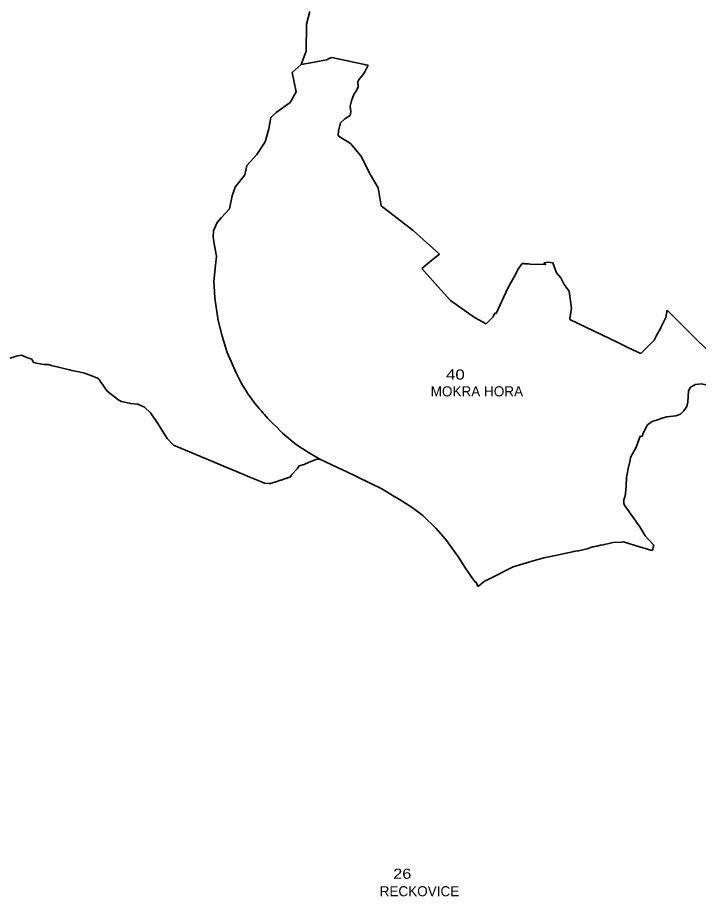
# Model space of a CAD drawing. Extents: x -610940 to -588976, y -1170376 to -1149800.
# Drawn here: x -599851 to -598167, y -1154630 to -1152456 of the extents above; entities that cross this region are included whole.
import ezdxf

# ---------------------------------------------------------------- set-up
doc = ezdxf.new("R2010")
doc.units = 0
doc.header["$LTSCALE"] = 10
doc.layers.add('54', color=7, linetype='Continuous', lineweight=35)
doc.layers.add('55', color=7, linetype='Continuous')
doc.layers.add('56', color=7, linetype='Continuous')

msp = doc.modelspace()

# ---------------------------------------------------------------- linework, layer by layer
at = {"layer": '54'}
for p, q in [((-599135.99, -1152472.46), (-599127.86, -1152441.09)), ((-599137.52, -1152539.3), (-599135.99, -1152472.46)), ((-599149.75, -1152572.15), (-599137.52, -1152539.3)), ((-599078.33, -1152556.67), (-599086.96, -1152560.86)), ((-599078.33, -1152556.67), (-599076.27, -1152555.67)), ((-599073.96, -1152554.47), (-599076.27, -1152555.67)), ((-598992.49, -1152572.39), (-599073.96, -1152554.47)), ((-599149.75, -1152572.15), (-599171.98, -1152591.48)), ((-598992.49, -1152572.39), (-598990.48, -1152572.63)), ((-598989.54, -1152572.74), (-598990.48, -1152572.63)), ((-598983.79, -1152573.41), (-598989.54, -1152572.74)), ((-599058.33, -1152748.38), (-599057.24, -1152736.51)), ((-599326.62, -1152928.89), (-599320.06, -1152896.63)), ((-598872.17, -1152982.37), (-598951.28, -1152921.55)), ((-599366.32, -1152983.61), (-599366.82, -1152998.36)), ((-598872.17, -1152982.37), (-598807.43, -1153041.24)), ((-599366.85, -1152999.45), (-599366.82, -1152998.36)), ((-599365.12, -1153010.27), (-599364.26, -1153015.45)), ((-599359.16, -1153045.95), (-599364.26, -1153015.45)), ((-599358.97, -1153047.01), (-599359.16, -1153045.95)), ((-598807.43, -1153041.24), (-598821.86, -1153053.07)), ((-598851.2, -1153077.1), (-598821.86, -1153053.07)), ((-598851.2, -1153077.1), (-598811.27, -1153121.37)), ((-598638.53, -1153125.57), (-598618.53, -1153090.33)), ((-599365.13, -1153108.85), (-599364.6, -1153119.76)), ((-599364.6, -1153119.76), (-599363.14, -1153149.9)), ((-598780.28, -1153155.74), (-598811.27, -1153121.37)), ((-598638.53, -1153125.57), (-598667.58, -1153188.27)), ((-599363.14, -1153149.9), (-599354.54, -1153205.53)), ((-598244.44, -1153179.9), (-598247.41, -1153198.37)), ((-598240.93, -1153183.4), (-598244.44, -1153179.9)), ((-598247.41, -1153198.37), (-598260.1, -1153222.84)), ((-598235.67, -1153188.66), (-598240.93, -1153183.4)), ((-598232.9, -1153191.43), (-598235.67, -1153188.66)), ((-599345.19, -1153244.24), (-599354.54, -1153205.53)), ((-598261.89, -1153226.48), (-598260.1, -1153222.84)), ((-598276.15, -1153253.71), (-598271.32, -1153244.46)), ((-598267.44, -1153237.03), (-598271.32, -1153244.46)), ((-598261.89, -1153226.48), (-598267.44, -1153237.03)), ((-598366.56, -1153260.04), (-598355.07, -1153265.54)), ((-598339.86, -1153272.82), (-598355.07, -1153265.54)), ((-598289.4, -1153266.97), (-598290.19, -1153267.76)), ((-598276.15, -1153253.71), (-598289.4, -1153266.97)), ((-598309.76, -1153287.28), (-598339.86, -1153272.82)), ((-598309.76, -1153287.28), (-598290.19, -1153267.76)), ((-599828.06, -1153297.24), (-599815.9, -1153301.5)), ((-599800.03, -1153311.45), (-599785.76, -1153314.4)), ((-599743, -1153322.93), (-599722.1, -1153327.59)), ((-599658.99, -1153345.62), (-599653.05, -1153347.81)), ((-599297.18, -1153361.27), (-599310.41, -1153334.84)), ((-599644.79, -1153358.26), (-599640.3, -1153364.57)), ((-599640.3, -1153364.57), (-599634.83, -1153372.08)), ((-599634.83, -1153372.08), (-599629.17, -1153380.26)), ((-599280.54, -1153387.7), (-599297.18, -1153361.27)), ((-599629.17, -1153380.26), (-599604.04, -1153400.11)), ((-598195.43, -1153418.01), (-598202.78, -1153429.25)), ((-599521.3, -1153434.97), (-599504.37, -1153460.09)), ((-599240.43, -1153437.86), (-599232.72, -1153446.72)), ((-599504.37, -1153460.09), (-599480.77, -1153497.73)), ((-599230.93, -1153448.77), (-599232.72, -1153446.72)), ((-598303.55, -1153484), (-598293.31, -1153463.21)), ((-598281.78, -1153454.91), (-598293.31, -1153463.21)), ((-598281.78, -1153454.91), (-598261.17, -1153448.5)), ((-598261.17, -1153448.5), (-598260.06, -1153448.16)), ((-598245.07, -1153443.49), (-598260.06, -1153448.16)), ((-599209.18, -1153470.55), (-599201.71, -1153478.03)), ((-599195.29, -1153484.45), (-599201.71, -1153478.03)), ((-598306.53, -1153492.78), (-598303.55, -1153484)), ((-599480.77, -1153497.73), (-599464.93, -1153514.21)), ((-598310.95, -1153491.41), (-598321.18, -1153519.22)), ((-598310.95, -1153491.41), (-598306.53, -1153492.78)), ((-599464.93, -1153514.21), (-599455.7, -1153518.06)), ((-599455.7, -1153518.06), (-599400.37, -1153541.23)), ((-598321.18, -1153519.22), (-598334.8, -1153544.12)), ((-599131.42, -1153556.78), (-599112.96, -1153549.04)), ((-599108.6, -1153545.04), (-599113.06, -1153542.5)), ((-599112.96, -1153549.04), (-599103.41, -1153548.24)), ((-599107.22, -1153545.82), (-599108.6, -1153545.04)), ((-599103.41, -1153548.24), (-599107.22, -1153545.82)), ((-599103.41, -1153548.24), (-599043.96, -1153576.27)), ((-598334.8, -1153544.12), (-598336.24, -1153550.96)), ((-599174.55, -1153587.84), (-599158.75, -1153571.19)), ((-599158.75, -1153571.19), (-599154.22, -1153565)), ((-599154.22, -1153565), (-599151.54, -1153564.24)), ((-599151.54, -1153564.24), (-599142.27, -1153561.36)), ((-599142.27, -1153561.36), (-599138.78, -1153560.45)), ((-599138.78, -1153560.45), (-599131.42, -1153556.78)), ((-598340.59, -1153571.58), (-598336.24, -1153550.96)), ((-599324.93, -1153572.68), (-599287.84, -1153588.14)), ((-599287.84, -1153588.14), (-599276.83, -1153592.73)), ((-599174.55, -1153587.84), (-599174.49, -1153588.06)), ((-598345.18, -1153593.29), (-598346.07, -1153614.94)), ((-599240.26, -1153607.98), (-599228.36, -1153608.86)), ((-598949.68, -1153621.51), (-598917.87, -1153641.37)), ((-598848.63, -1153687.99), (-598875.06, -1153668.48)), ((-598418.64, -1153763.65), (-598408.81, -1153761.47)), ((-598408.81, -1153761.47), (-598402.93, -1153760.17)), ((-598399.81, -1153759.48), (-598402.93, -1153760.17)), ((-598399.69, -1153760.02), (-598399.81, -1153759.48)), ((-598377.92, -1153754.94), (-598399.69, -1153760.02)), ((-598377.92, -1153754.94), (-598357.22, -1153753.45)), ((-598352.73, -1153753.39), (-598357.22, -1153753.45)), ((-598352.73, -1153753.39), (-598310.36, -1153765.86)), ((-598297.62, -1153769.61), (-598304.38, -1153767.62)), ((-598549.01, -1153792.72), (-598520.86, -1153786.71)), ((-598520.86, -1153786.71), (-598520.14, -1153786.56)), ((-598520.14, -1153786.56), (-598478.29, -1153777.62)), ((-598478.29, -1153777.62), (-598475.91, -1153777.27)), ((-598475.91, -1153777.27), (-598465.69, -1153775.56)), ((-598297.62, -1153769.61), (-598290.86, -1153771.6)), ((-598285.24, -1153773.25), (-598290.86, -1153771.6)), ((-598281.28, -1153774.42), (-598285.24, -1153773.25)), ((-598598.07, -1153806.95), (-598594.82, -1153805.96)), ((-598594.82, -1153805.96), (-598576.14, -1153800.26)), ((-598560.51, -1153795.86), (-598576.14, -1153800.26)), ((-598551.98, -1153793.37), (-598560.51, -1153795.86)), ((-598549.58, -1153792.84), (-598551.98, -1153793.37)), ((-598549.01, -1153792.72), (-598549.58, -1153792.84)), ((-598744.48, -1153816), (-598730.63, -1153836.02)), ((-598719.22, -1153853.21), (-598730.63, -1153836.02)), ((-598688.57, -1153846.89), (-598689.98, -1153847.52)), ((-598686.98, -1153846.18), (-598688.57, -1153846.89)), ((-598685.75, -1153845.63), (-598686.98, -1153846.18)), ((-598713.46, -1153861.1), (-598712.61, -1153863.28)), ((-598712.61, -1153863.28), (-598710.27, -1153861.52)), ((-598710.27, -1153861.52), (-598707.07, -1153859.11)), ((-598707.07, -1153859.11), (-598705.28, -1153857.76)), ((-598705.28, -1153857.76), (-598704.94, -1153857.51))]:
    msp.add_line(p, q, dxfattribs=at)
for points in [[(-599086.96, -1152560.86), (-599116.99, -1152566.22), (-599121.58, -1152567.01), (-599149.75, -1152572.15)], [(-599171.98, -1152591.48), (-599161.5, -1152639.33), (-599176.48, -1152665.73), (-599211.71, -1152691.23), (-599224.57, -1152703.19), (-599229.52, -1152731.35), (-599238.51, -1152763.37), (-599259.43, -1152794.76)], [(-598983.79, -1152573.41), (-598992.76, -1152591.49), (-598999.74, -1152600.82), (-599005.21, -1152607.32), (-599009.17, -1152614.28), (-599008.61, -1152628.23), (-599014.67, -1152639.22), (-599019.34, -1152645.93), (-599024.7, -1152662.11), (-599028.46, -1152675.36), (-599026.32, -1152689.13), (-599028.7, -1152698.59), (-599041.9, -1152706.56), (-599052.46, -1152716.11), (-599057.24, -1152736.51)], [(-599058.33, -1152748.38), (-599027.5, -1152767.8), (-599001.64, -1152798.37)], [(-599288.48, -1152844.94), (-599283.65, -1152821.65), (-599259.43, -1152794.76)], [(-599001.64, -1152798.37), (-598978, -1152845.22), (-598958.96, -1152877.21), (-598951.28, -1152921.55)], [(-599288.48, -1152844.94), (-599313.01, -1152875.39), (-599320.06, -1152896.63)], [(-599326.62, -1152928.89), (-599346.47, -1152950.7), (-599356.63, -1152961.87)], [(-599356.63, -1152961.87), (-599357.79, -1152964.48), (-599366.32, -1152983.61)], [(-599366.85, -1152999.45), (-599366.19, -1153003.87), (-599365.12, -1153010.27)], [(-599358.97, -1153047.01), (-599361.12, -1153068.59), (-599365.13, -1153108.85)], [(-598538.39, -1153061.2), (-598548.81, -1153063.05), (-598545.06, -1153067.23), (-598583.35, -1153066.18), (-598587.63, -1153065.54), (-598590.47, -1153065.48), (-598592.37, -1153065.41), (-598594.37, -1153065.14), (-598596.23, -1153064.99), (-598597.77, -1153064.73), (-598599.22, -1153064.51), (-598600.85, -1153064.29), (-598602.87, -1153064.16), (-598613.24, -1153078.88), (-598618.53, -1153090.33)], [(-598487.07, -1153132.6), (-598499.26, -1153116.32), (-598506.91, -1153099.64), (-598517.83, -1153087.52), (-598526.81, -1153062.81), (-598538.39, -1153061.2)], [(-598366.56, -1153260.04), (-598484.75, -1153202.93), (-598484.97, -1153199.95), (-598480.99, -1153175.42), (-598487.07, -1153132.6)], [(-598692.17, -1153213.47), (-598721.13, -1153198.42), (-598780.28, -1153155.74)], [(-598667.58, -1153188.27), (-598670.39, -1153187.02), (-598674.89, -1153195.99), (-598692.17, -1153213.47)], [(-598138.68, -1153284.83), (-598183.64, -1153241.04), (-598232.9, -1153191.43)], [(-599345.19, -1153244.24), (-599332.1, -1153284.2), (-599310.41, -1153334.84)], [(-599876.61, -1153301.06), (-599854.53, -1153293.86), (-599840.76, -1153291.57), (-599828.06, -1153297.24)], [(-599815.9, -1153301.5), (-599811.7, -1153309.01), (-599807.18, -1153309.91), (-599800.03, -1153311.45)], [(-599785.76, -1153314.4), (-599775.21, -1153314.12), (-599766.8, -1153316.47), (-599743, -1153322.93)], [(-599722.1, -1153327.59), (-599716.29, -1153328.89), (-599699.37, -1153332.67), (-599684.96, -1153336.06), (-599666.98, -1153342.68), (-599658.99, -1153345.62)], [(-599653.05, -1153347.81), (-599651.54, -1153348.75), (-599649.44, -1153351.7), (-599644.79, -1153358.26)], [(-597929.63, -1153420.15), (-597953.19, -1153411.6), (-597972.61, -1153408.03), (-598002.32, -1153411.31), (-598021.65, -1153409.35), (-598049.68, -1153401.31), (-598077.93, -1153399.17), (-598097.24, -1153392.34), (-598116.69, -1153380.62), (-598140.09, -1153366.01), (-598160.27, -1153362.42), (-598174.63, -1153363.77), (-598186.36, -1153370.45), (-598191.41, -1153379.44), (-598193.27, -1153407.64), (-598195.43, -1153418.01)], [(-599280.54, -1153387.7), (-599271.84, -1153399.75), (-599265.43, -1153408.62), (-599263.31, -1153411.56)], [(-599604.04, -1153400.11), (-599603.23, -1153400.57), (-599594.74, -1153405.42)], [(-599594.74, -1153405.42), (-599593.45, -1153405.72), (-599574.84, -1153410.11)], [(-599574.84, -1153410.11), (-599574.08, -1153410.29), (-599573.75, -1153410.33), (-599570.7, -1153410.67), (-599555.14, -1153412.4)], [(-599555.14, -1153412.4), (-599553.13, -1153412.62), (-599536.99, -1153419.77), (-599521.3, -1153434.97)], [(-599263.31, -1153411.56), (-599258.29, -1153417.32), (-599252.95, -1153423.46), (-599247.12, -1153430.17)], [(-599247.12, -1153430.17), (-599243.19, -1153434.85), (-599240.43, -1153437.86)], [(-598202.78, -1153429.25), (-598211.7, -1153437.12), (-598222.84, -1153441.14), (-598245.07, -1153443.49)], [(-599230.93, -1153448.77), (-599221.43, -1153458.28), (-599209.18, -1153470.55)], [(-599164.99, -1153509.89), (-599190.81, -1153488.06), (-599195.29, -1153484.45)], [(-599145.13, -1153523.29), (-599150.87, -1153519.42), (-599164.99, -1153509.89)], [(-599113.06, -1153542.5), (-599131.08, -1153531.63), (-599145.13, -1153523.29)], [(-599400.37, -1153541.23), (-599391.04, -1153545.12), (-599390.53, -1153545.33), (-599370.77, -1153553.57), (-599327.37, -1153571.66)], [(-599327.37, -1153571.66), (-599326.82, -1153571.89), (-599324.93, -1153572.68)], [(-598340.59, -1153571.58), (-598341.41, -1153575.47), (-598343.63, -1153585.95), (-598345.18, -1153593.29)], [(-599276.83, -1153592.73), (-599251.42, -1153603.33), (-599240.26, -1153607.98)], [(-599187.98, -1153596.35), (-599186.98, -1153596.02), (-599183.59, -1153594.86), (-599175.02, -1153591.95)], [(-599175.02, -1153591.95), (-599174.66, -1153590.07), (-599174.49, -1153588.06)], [(-599043.96, -1153576.27), (-599040.14, -1153578.09), (-598949.68, -1153621.51)], [(-599228.36, -1153608.86), (-599225.36, -1153609.06), (-599209.31, -1153603.6), (-599206.88, -1153602.77), (-599203.38, -1153601.58), (-599200.33, -1153600.55), (-599199.22, -1153600.17), (-599187.98, -1153596.35)], [(-598347.77, -1153635.93), (-598347.56, -1153633.35), (-598346.07, -1153614.94)], [(-598347.77, -1153635.93), (-598351.96, -1153652.15), (-598351.75, -1153654.16)], [(-598917.87, -1153641.37), (-598913.05, -1153644.39), (-598906.41, -1153648.53), (-598875.06, -1153668.48)], [(-598351.75, -1153654.16), (-598351.32, -1153658.14), (-598351.03, -1153660.88)], [(-598311.6, -1153716.26), (-598348.15, -1153664.93), (-598351.03, -1153660.88)], [(-598792.54, -1153746.41), (-598816.17, -1153719.12), (-598848.63, -1153687.99)], [(-598311.6, -1153716.26), (-598304.35, -1153728.62), (-598298.95, -1153737.86), (-598290.49, -1153746.96), (-598277.14, -1153761.32)], [(-598792.54, -1153746.41), (-598761.8, -1153788.64), (-598744.48, -1153816)], [(-598465.69, -1153775.56), (-598463.58, -1153775.25), (-598442.46, -1153770.18), (-598427.87, -1153765.03), (-598418.64, -1153763.65)], [(-598310.36, -1153765.86), (-598306.19, -1153767.09), (-598304.38, -1153767.62)], [(-598281.28, -1153774.42), (-598280.75, -1153772.75), (-598277.14, -1153761.32)], [(-598685.75, -1153845.63), (-598624.82, -1153814.68), (-598611.39, -1153810.87), (-598598.07, -1153806.95)], [(-598719.22, -1153853.21), (-598716.6, -1153853.05), (-598713.46, -1153861.1)], [(-598704.94, -1153857.51), (-598696.72, -1153850.81), (-598694.31, -1153849.48)], [(-598689.98, -1153847.52), (-598691.06, -1153848.01), (-598694.31, -1153849.48)]]:
    msp.add_lwpolyline(points, dxfattribs=at)

# ---------------------------------------------------------------- texts
at = {"layer": '55'}
for s, p in [('MOKRA HORA', (-598829.16, -1153393.22)), ('RECKOVICE ', (-598955.42, -1154629.93))]:
    msp.add_text(s, height=25, dxfattribs=at).set_placement(p)
at = {"layer": '56'}
for s, width, p in [('40 ', 1.25, (-598791.35, -1153351.57)), ('26 ', 1.2, (-598921.74, -1154586.62))]:
    msp.add_text(s, height=25, dxfattribs=dict(at, width=width)).set_placement(p)

doc.saveas('drawing.dxf')
